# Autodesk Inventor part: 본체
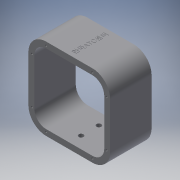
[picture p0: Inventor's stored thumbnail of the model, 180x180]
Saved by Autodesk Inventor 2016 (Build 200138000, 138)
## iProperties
Created: 2016-12
Part Number: 본체
Material: 알루미늄 6061
Document SubType Name: Modeling
Designer: mduedu
Density: 2.71 g/cm^3
Appearance: 기본값
Mass: 883.341 g
Surface Area: 772.714 cm^2
Volume: 325.956 cm^3
Author: mduedu
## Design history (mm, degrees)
sketch "스케치1"
  geometry: L1 (-46, 42)-(-46, -36); L2 (-16, 72)-(62, 72); L3 (92, 42)-(92, -36); L4 (62, -66)-(-16, -66); A1 r 30 centre (-16, -36) between (-46, -36) and (-16, -66); A2 r 30 centre (62, 42) between (92, 42) and (62, 72); A3 r 30 centre (62, -36) between (62, -66) and (92, -36); A4 r 30 centre (-16, 42) between (-16, 72) and (-46, 42); 1 further point
  constraints: 8 end point, 8 point on circle, 8 tangent, 4 centre point, 3 equal radius, 1 horizontal, 1 perpendicular, 1 vertical
  dimensions: "d83" = 30 radius of A2; "d84" = 92 distance from line of L3 point (0, 0); "d85" = 138 distance between parallel lines of L4 L2; "d86" = 46 distance from line of L1 point (0, 0); "d87" = 72 distance from line of point (0, 0) L2
extrude "돌출1" new body sketch "스케치1" stored distance "d3" = 70; taper "d4" = 0 deg
feature "쉘1" dims "d5" = 10
sketch "스케치10"
  geometry: L1 (78, 70)-(0, 70) reference; L2 (-30, 70)-(-30, 0) reference; 4 further points
  constraints: 1 coincident, 1 horizontal alignment, 1 midpoint, 1 vertical alignment, 1 other
  dimensions: "d88" = 35 distance of point (39, 35) point (39, 70) (derived); "d89" = 69 distance from line of point (39, 35) L2 (derived)
feature "엠보싱1" sketch "스케치10" dims "d61" = 0.5, "d62" = 0, "d83" = 30, "d84" = 92, "d85" = 138, "d86" = 46, "d87" = 72
sketch "스케치11"
  geometry: L1 (-36, -36)-(-36, 42) reference; L2 (-16, 62)-(62, 62) reference; L3 (82, 42)-(82, -36) reference; L4 (62, -56)-(-16, -56) reference; L5 (-16, -66)-(62, -66) reference; L6 (92, -36)-(92, 42) reference; L7 (62, 72)-(-16, 72) reference; L8 (-46, 42)-(-46, -36) reference; L9 (-16, 66)-(62, 66); L10 (86, 42)-(86, -36); L11 (62, -60)-(-16, -60); L12 (-40, -36)-(-40, 42); A1 r 20 centre (-16, -36) between (-36, -36) and (-16, -56) reference; A2 r 20 centre (-16, 42) between (-16, 62) and (-36, 42) reference; A3 r 20 centre (62, 42) between (82, 42) and (62, 62) reference; A4 r 20 centre (62, -36) between (62, -56) and (82, -36) reference; A5 r 30 centre (-16, -36) between (-46, -36) and (-16, -66) reference; A6 r 30 centre (62, -36) between (62, -66) and (92, -36) reference; A7 r 30 centre (62, 42) between (92, 42) and (62, 72) reference; A8 r 30 centre (-16, 42) between (-16, 72) and (-46, 42) reference; A9 r 24 centre (62, 42) between (86, 42) and (62, 66); A10 r 24 centre (62, -36) between (62, -60) and (86, -36); A11 r 24 centre (-16, -36) between (-40, -36) and (-16, -60); A12 r 24 centre (-16, 42) between (-16, 66) and (-40, 42); 8 further points
  constraints: 8 coincident, 8 end point, 8 point on circle, 4 centre point, 7 other
  dimensions: "d90" = 6 distance between parallel lines of L9 L7
hole "구멍3" sketch "스케치11" at (-16, 66), (-40, 42), (-40, -36), (-16, -60), (62, -60), (86, -36), (86, 42), (62, 66) diameter "d63" = 3.242; stored, may be unused: countersink angle "d67" = 90 deg, drill point angle "d69" = 120 deg; dims "d64" = 8.6, "d65" = 4, "d66" = 2, "d68" = 10.6
sketch "스케치12"
  geometry: L1 (16, -56)-(-62, -56) reference; L2 (-82, -36)-(-82, 42) reference; L3 (-62, 62)-(16, 62) reference; L4 (36, 42)-(36, -36) reference; L5 (46, -36)-(46, 42) reference; L6 (16, 72)-(-62, 72) reference; L7 (-92, 42)-(-92, -36) reference; L8 (-62, -66)-(16, -66) reference; L9 (-62, 66)-(16, 66); L10 (40, 42)-(40, -36); L11 (16, -60)-(-62, -60); L12 (-86, -36)-(-86, 42); A1 r 20 centre (16, -36) between (16, -56) and (36, -36) reference; A2 r 20 centre (-62, -36) between (-82, -36) and (-62, -56) reference; A3 r 20 centre (-62, 42) between (-62, 62) and (-82, 42) reference; A4 r 20 centre (16, 42) between (36, 42) and (16, 62) reference; A5 r 30 centre (16, -36) between (16, -66) and (46, -36) reference; A6 r 30 centre (16, 42) between (46, 42) and (16, 72) reference; A7 r 30 centre (-62, 42) between (-62, 72) and (-92, 42) reference; A8 r 30 centre (-62, -36) between (-92, -36) and (-62, -66) reference; A9 r 24 centre (16, 42) between (40, 42) and (16, 66); A10 r 24 centre (16, -36) between (16, -60) and (40, -36); A11 r 24 centre (-62, -36) between (-86, -36) and (-62, -60); A12 r 24 centre (-62, 42) between (-62, 66) and (-86, 42); 8 further points
  constraints: 8 coincident, 8 end point, 8 point on circle, 4 centre point, 7 other
  dimensions: "d91" = 6 distance between parallel lines of L9 L6
hole "구멍5" sketch "스케치12" at (-62, 66), (-86, 42), (-86, -36), (-62, -60), (16, -60), (40, -36), (40, 42), (16, 66) diameter "d70" = 3.242; stored, may be unused: countersink angle "d74" = 90 deg, drill point angle "d76" = 120 deg; dims "d71" = 8.6, "d72" = 4, "d73" = 2, "d75" = 10.6
sketch "스케치15"
  geometry: L1 (135.6, -35)-(-57.6, -35) reference; L2 (78, 0)-(0, 0) reference; L3 (0, -70)-(78, -70) reference; L4 (39, 0)-(39, -70); C1 r 4 at (39, -20); C2 r 4 at (39, -50); 1 further point
  constraints: 2 centre point, 2 end point, 2 midpoint, 1 point on line, 1 symmetric about line, 1 other
  dimensions: "d92" = 8 diameter of C1; "d93" = 15 distance from line of C1.centre L1
extrude "돌출6" cut sketch "스케치15" stored distance "d94" = 10; taper "d95" = 0 deg
node "솔리드1"
node "투영된 루프3"
node "투영된 루프4"
